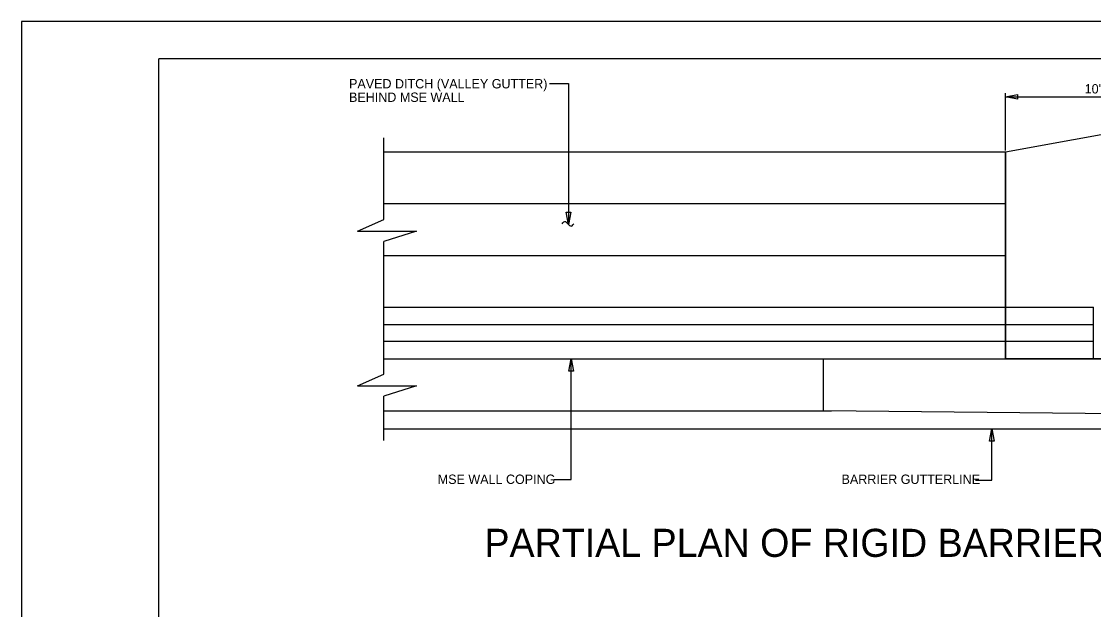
# Model space of a CAD drawing. Extents: x 96 to 240, y 601 to 689.
# Drawn here: x 95.8 to 153.1, y 657.6 to 689 of the extents above; entities that cross this region are included whole.
import ezdxf

# ---------------------------------------------------------------- set-up
doc = ezdxf.new("R2010")
doc.units = 0
for name, color, linetype in [('BR_AUTO DIMENSION', 7, 'Continuous'), ('BR_BORDER LINES', 7, 'Continuous'), ('BR_CONCRETE', 7, 'Continuous'), ('BR_TEXT', 7, 'Continuous'), ('Level 31', 7, 'Continuous')]:
    doc.layers.add(name, color=color, linetype=linetype)

msp = doc.modelspace()

# ---------------------------------------------------------------- linework, layer by layer
at = {"layer": 'BR_AUTO DIMENSION'}
for p, q in [((124.033, 685.686), (125.041, 685.686)), ((125.041, 685.686), (125.041, 678.176)), ((148.363, 682.108), (148.363, 685.177)), ((148.363, 684.981), (159.066, 684.981)), ((115.181, 678.434), (115.181, 682.797)), ((113.78, 677.819), (115.181, 678.434)), ((113.78, 677.819), (116.921, 677.819)), ((116.921, 677.819), (115.181, 677.254)), ((115.181, 670.181), (115.181, 677.254)), ((125.185, 664.568), (125.185, 670.994)), ((113.78, 669.566), (115.181, 670.181)), ((113.78, 669.566), (116.921, 669.566)), ((116.921, 669.566), (115.181, 669.001)), ((115.181, 666.643), (115.181, 669.001)), ((147.635, 664.515), (147.635, 667.262)), ((124.277, 664.568), (125.185, 664.568)), ((146.762, 664.515), (147.635, 664.515))]:
    msp.add_line(p, q, dxfattribs=at)
for points in [[(149.013, 684.856), (148.363, 684.981), (149.013, 685.106)], [(125.166, 678.826), (125.041, 678.176), (124.916, 678.826)], [(125.06, 670.344), (125.185, 670.994), (125.31, 670.344)], [(147.51, 666.612), (147.635, 667.262), (147.76, 666.612)]]:
    msp.add_lwpolyline(points, close=True, dxfattribs=at)
at = {"layer": 'BR_BORDER LINES'}
for p in [(237.837, 687.003), (103.173, 603.003)]:
    msp.add_line(p, (103.173, 687.003), dxfattribs=at)
at = {"layer": 'BR_CONCRETE'}
for p, q in [((115.181, 682.045), (148.363, 682.045)), ((148.363, 682.045), (148.363, 673.757)), ((148.363, 682.045), (148.363, 670.994)), ((115.181, 679.283), (148.363, 679.283)), ((115.181, 676.52), (148.363, 676.52)), ((115.181, 673.757), (148.363, 673.757)), ((148.363, 673.757), (153.066, 673.757)), ((153.066, 670.994), (153.066, 673.757)), ((115.181, 672.836), (153.066, 672.836)), ((153.066, 671.915), (115.181, 671.915)), ((115.181, 670.994), (161.649, 670.994)), ((115.181, 670.994), (148.363, 670.994)), ((138.644, 668.232), (138.644, 670.994)), ((115.181, 668.232), (138.644, 668.232)), ((161.649, 667.994), (138.644, 668.232)), ((115.181, 667.262), (158.46, 667.262))]:
    msp.add_line(p, q, dxfattribs=at)
at = {"layer": 'BR_TEXT'}
for p, q in [((124.704, 678.204), (124.734, 678.25)), ((124.938, 678.271), (125.101, 678.121)), ((125.279, 678.143), (125.322, 678.204))]:
    msp.add_line(p, q, dxfattribs=at)
msp.add_lwpolyline([(159.066, 670.994), (148.363, 670.994), (148.363, 682.045), (159.066, 683.99)], close=True, dxfattribs=at)
for centre, radius, start, end in [((124.844, 678.189), 0.125, 41.007, 150.8059), ((125.181, 678.196), 0.111, 223.4519, 331.7375)]:
    msp.add_arc(centre, radius, start, end, dxfattribs=at)
at = {"layer": 'Level 31'}
for p, q in [((239.84, 689.004), (95.84, 689.004)), ((138.644, 668.232), (139.072, 668.232))]:
    msp.add_line(p, q, dxfattribs=at)
msp.add_lwpolyline([(95.84, 689.004), (95.84, 601.004), (239.84, 601.004), (239.84, 689.004)], dxfattribs=at)

# ---------------------------------------------------------------- texts
at = {"layer": 'BR_AUTO DIMENSION'}
for s, p in [('PAVED DITCH (VALLEY GUTTER)', (113.326, 685.43)), ('10\'-0"', (152.593, 685.16)), ('BEHIND MSE WALL', (113.326, 684.71)), ('MSE WALL COPING', (118.061, 664.323)), ('BARRIER GUTTERLINE', (139.615, 664.323))]:
    msp.add_text(s, height=0.5, dxfattribs=at).set_placement(p)
at = {"layer": 'BR_TEXT'}
msp.add_text('PARTIAL PLAN OF RIGID BARRIER - MSE WALL', height=1.5, dxfattribs=at).set_placement((120.556, 660.429))

doc.saveas('drawing.dxf')
